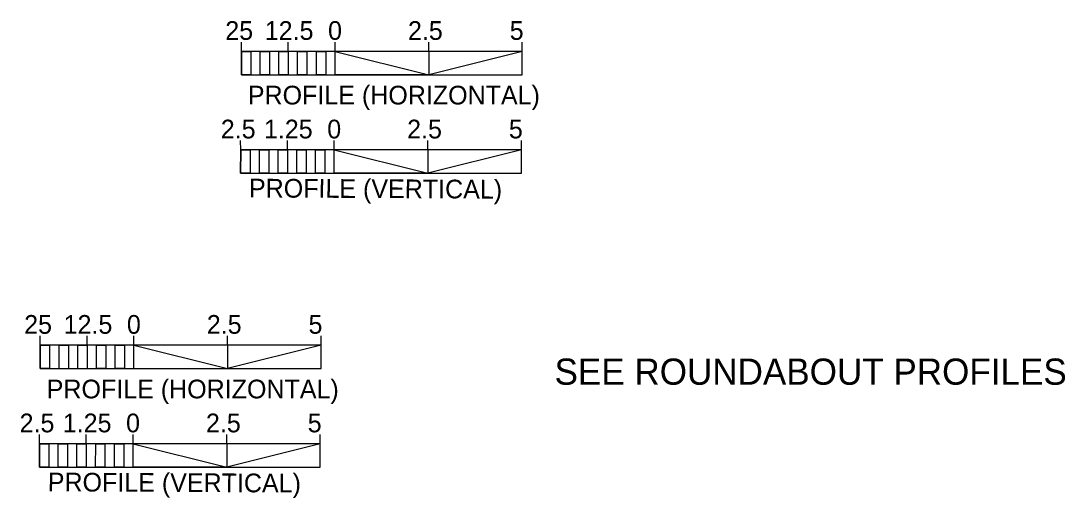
# Model space of a CAD drawing. Extents: x 557032 to 562069, y 513430 to 515874.
# Drawn here: x 558729.4 to 559008.3, y 514518.9 to 514646.4 of the extents above; entities that cross this region are included whole.
import ezdxf

# ---------------------------------------------------------------- set-up
doc = ezdxf.new("R2010")
doc.units = 0
doc.layers.add('Exist CMT Ground Line', color=7, linetype='Continuous')
doc.layers.add('Sheet Title CELL', color=7, linetype='Continuous')

msp = doc.modelspace()

# ---------------------------------------------------------------- linework, layer by layer
at = {"layer": 'Sheet Title CELL'}
for p, q in [((558788.35, 514638.22), (558788.35, 514640.73)), ((558788.35, 514638.22), (558788.35, 514640.73)), ((558788.35, 514640.73), (558788.35, 514640.73)), ((558800.86, 514638.22), (558800.85, 514640.73)), ((558800.86, 514638.22), (558800.85, 514640.73)), ((558813.35, 514638.23), (558813.35, 514640.72)), ((558813.35, 514638.23), (558813.35, 514640.72)), ((558838.35, 514638.23), (558838.35, 514640.73)), ((558838.35, 514638.23), (558838.35, 514640.73)), ((558863.35, 514638.23), (558863.36, 514640.73)), ((558863.35, 514638.23), (558863.36, 514640.73)), ((558863.35, 514638.23), (558788.35, 514638.22)), ((558863.35, 514638.23), (558788.35, 514638.22)), ((558788.35, 514638.22), (558788.35, 514631.98)), ((558788.35, 514638.22), (558788.35, 514638.22)), ((558788.35, 514638.22), (558788.35, 514638.22)), ((558805.85, 514638.22), (558805.85, 514631.98)), ((558838.35, 514638.23), (558838.35, 514631.98)), ((558863.35, 514631.98), (558863.35, 514638.23)), ((558788.35, 514631.98), (558863.35, 514631.98)), ((558788.14, 514611.89), (558788.13, 514614.4)), ((558788.14, 514611.89), (558788.13, 514614.4)), ((558788.14, 514611.89), (558788.13, 514614.4)), ((558788.13, 514614.4), (558788.13, 514614.4)), ((558800.63, 514611.9), (558800.63, 514614.39)), ((558800.63, 514611.9), (558800.63, 514614.39)), ((558800.63, 514611.9), (558800.63, 514614.39)), ((558813.13, 514611.9), (558813.14, 514614.39)), ((558813.13, 514611.9), (558813.14, 514614.39)), ((558813.13, 514611.9), (558813.14, 514614.39)), ((558838.13, 514611.89), (558838.13, 514614.4)), ((558838.13, 514611.89), (558838.13, 514614.4)), ((558838.13, 514611.89), (558838.13, 514614.4)), ((558863.13, 514611.9), (558863.13, 514614.39)), ((558863.13, 514611.9), (558863.13, 514614.39)), ((558863.13, 514611.9), (558863.13, 514614.39)), ((558788.14, 514611.89), (558788.13, 514605.65)), ((558863.13, 514611.9), (558788.14, 514611.89)), ((558863.13, 514611.9), (558788.14, 514611.89)), ((558863.13, 514611.9), (558788.14, 514611.89)), ((558788.14, 514611.89), (558788.14, 514611.89)), ((558788.14, 514611.89), (558788.14, 514611.89)), ((558788.14, 514611.89), (558788.14, 514611.89)), ((558805.63, 514611.89), (558805.63, 514605.64)), ((558838.13, 514611.89), (558838.13, 514605.64)), ((558863.13, 514605.65), (558863.13, 514611.9)), ((558788.13, 514605.65), (558863.13, 514605.65)), ((558734.62, 514559.69), (558734.62, 514562.2)), ((558734.62, 514559.69), (558734.62, 514562.2)), ((558734.62, 514562.2), (558734.62, 514562.2)), ((558809.62, 514559.7), (558734.62, 514559.69)), ((558809.62, 514559.7), (558734.62, 514559.69)), ((558734.62, 514559.69), (558734.62, 514553.45)), ((558734.62, 514559.69), (558734.62, 514559.69)), ((558734.62, 514559.69), (558734.62, 514559.69)), ((558747.13, 514559.69), (558747.12, 514562.2)), ((558747.13, 514559.69), (558747.12, 514562.2)), ((558752.12, 514559.69), (558752.12, 514553.45)), ((558759.62, 514559.7), (558759.62, 514562.19)), ((558759.62, 514559.7), (558759.62, 514562.19)), ((558784.62, 514559.7), (558784.62, 514562.2)), ((558784.62, 514559.7), (558784.62, 514562.2)), ((558784.62, 514559.7), (558784.62, 514553.45)), ((558809.62, 514559.7), (558809.63, 514562.2)), ((558809.62, 514559.7), (558809.63, 514562.2)), ((558809.62, 514553.45), (558809.62, 514559.7)), ((558734.62, 514553.45), (558809.62, 514553.45)), ((558734.41, 514533.36), (558734.4, 514535.87)), ((558734.41, 514533.36), (558734.4, 514535.87)), ((558734.41, 514533.36), (558734.4, 514535.87)), ((558734.4, 514535.87), (558734.4, 514535.87)), ((558746.9, 514533.37), (558746.9, 514535.86)), ((558746.9, 514533.37), (558746.9, 514535.86)), ((558746.9, 514533.37), (558746.9, 514535.86)), ((558759.4, 514533.37), (558759.41, 514535.86)), ((558759.4, 514533.37), (558759.41, 514535.86)), ((558759.4, 514533.37), (558759.41, 514535.86)), ((558784.4, 514533.36), (558784.4, 514535.87)), ((558784.4, 514533.36), (558784.4, 514535.87)), ((558784.4, 514533.36), (558784.4, 514535.87)), ((558809.4, 514533.37), (558809.4, 514535.86)), ((558809.4, 514533.37), (558809.4, 514535.86)), ((558809.4, 514533.37), (558809.4, 514535.86)), ((558734.41, 514533.36), (558734.4, 514527.12)), ((558809.4, 514533.37), (558734.41, 514533.36)), ((558809.4, 514533.37), (558734.41, 514533.36)), ((558809.4, 514533.37), (558734.41, 514533.36)), ((558734.41, 514533.36), (558734.41, 514533.36)), ((558734.41, 514533.36), (558734.41, 514533.36)), ((558734.41, 514533.36), (558734.41, 514533.36)), ((558751.9, 514533.36), (558751.9, 514527.11)), ((558784.4, 514533.36), (558784.4, 514527.11)), ((558809.4, 514527.12), (558809.4, 514533.37)), ((558734.4, 514527.12), (558809.4, 514527.12))]:
    msp.add_line(p, q, dxfattribs=at)
for points in [[(558788.35, 514638.22), (558790.85, 514638.23), (558790.85, 514631.98), (558788.35, 514631.98)], [(558793.35, 514638.23), (558795.85, 514638.23), (558795.86, 514631.97), (558793.35, 514631.98)], [(558798.35, 514638.23), (558800.86, 514638.22), (558800.85, 514631.98), (558798.35, 514631.97)], [(558803.35, 514638.22), (558805.85, 514638.22), (558805.85, 514631.98), (558803.35, 514631.98)], [(558808.35, 514638.23), (558810.85, 514638.23), (558810.85, 514631.98), (558808.35, 514631.98)], [(558813.35, 514638.23), (558838.35, 514631.98), (558813.35, 514631.97)], [(558863.35, 514638.23), (558838.35, 514631.98), (558863.35, 514631.98)], [(558788.14, 514611.89), (558790.63, 514611.89), (558790.63, 514605.64), (558788.13, 514605.65)], [(558793.13, 514611.9), (558795.63, 514611.9), (558795.63, 514605.65), (558793.13, 514605.65)], [(558798.13, 514611.9), (558800.63, 514611.9), (558800.63, 514605.64), (558798.13, 514605.65)], [(558803.14, 514611.89), (558805.63, 514611.89), (558805.63, 514605.64), (558803.13, 514605.65)], [(558808.13, 514611.89), (558810.63, 514611.9), (558810.63, 514605.65), (558808.13, 514605.65)], [(558813.13, 514611.9), (558838.13, 514605.64), (558813.13, 514605.65)], [(558863.13, 514611.9), (558838.13, 514605.64), (558863.13, 514605.65)], [(558734.62, 514559.69), (558737.12, 514559.7), (558737.12, 514553.45), (558734.62, 514553.45)], [(558739.62, 514559.7), (558742.12, 514559.7), (558742.13, 514553.44), (558739.62, 514553.45)], [(558744.62, 514559.7), (558747.13, 514559.69), (558747.12, 514553.45), (558744.62, 514553.44)], [(558749.62, 514559.69), (558752.12, 514559.69), (558752.12, 514553.45), (558749.62, 514553.45)], [(558754.62, 514559.7), (558757.12, 514559.7), (558757.12, 514553.45), (558754.62, 514553.45)], [(558759.62, 514559.7), (558784.62, 514553.45), (558759.62, 514553.44)], [(558809.62, 514559.7), (558784.62, 514553.45), (558809.62, 514553.45)], [(558734.41, 514533.36), (558736.9, 514533.36), (558736.9, 514527.11), (558734.4, 514527.12)], [(558739.4, 514533.37), (558741.9, 514533.37), (558741.9, 514527.12), (558739.4, 514527.12)], [(558744.4, 514533.37), (558746.9, 514533.37), (558746.9, 514527.11), (558744.4, 514527.12)], [(558749.41, 514533.36), (558751.9, 514533.36), (558751.9, 514527.11), (558749.4, 514527.12)], [(558754.4, 514533.36), (558756.9, 514533.37), (558756.9, 514527.12), (558754.4, 514527.12)], [(558759.4, 514533.37), (558784.4, 514527.11), (558759.4, 514527.12)], [(558809.4, 514533.37), (558784.4, 514527.11), (558809.4, 514527.12)]]:
    msp.add_lwpolyline(points, close=True, dxfattribs=at)

# ---------------------------------------------------------------- texts
at = {"layer": 'Exist CMT Ground Line'}
msp.add_text('SEE ROUNDABOUT PROFILES', height=7, dxfattribs=at).set_placement((558871.97, 514549.15))
at = {"layer": 'Sheet Title CELL'}
for s, rotation, p in [('25', 360, (558784.03, 514641.3)), ('12.5', 360, (558794.57, 514641.3)), ('0', 360, (558811.48, 514641.3)), ('2.5', 360, (558832.82, 514641.3)), ('5', 360, (558859.99, 514641.3)), ('PROFILE (HORIZONTAL)', 360, (558790.05, 514624.04)), ('2.5', 360, (558782.83, 514614.97)), ('1.25', 360, (558794.35, 514614.97)), ('0', 360, (558811.26, 514614.97)), ('2.5', 360, (558832.6, 514614.97)), ('5', 360, (558859.77, 514614.97)), ('PROFILE (VERTICAL)', 359.7282, (558790.34, 514599.2)), ('25', 360, (558730.31, 514562.77)), ('12.5', 360, (558740.85, 514562.77)), ('0', 360, (558757.75, 514562.77)), ('2.5', 360, (558779.09, 514562.77)), ('5', 360, (558806.26, 514562.77)), ('PROFILE (HORIZONTAL)', 360, (558736.33, 514545.51)), ('2.5', 360, (558729.1, 514536.44)), ('1.25', 360, (558740.63, 514536.44)), ('0', 360, (558757.53, 514536.44)), ('2.5', 360, (558778.87, 514536.44)), ('5', 360, (558806.04, 514536.44)), ('PROFILE (VERTICAL)', 359.7282, (558736.61, 514520.67))]:
    msp.add_text(s, height=5, rotation=rotation, dxfattribs=at).set_placement(p)

doc.saveas('drawing.dxf')
